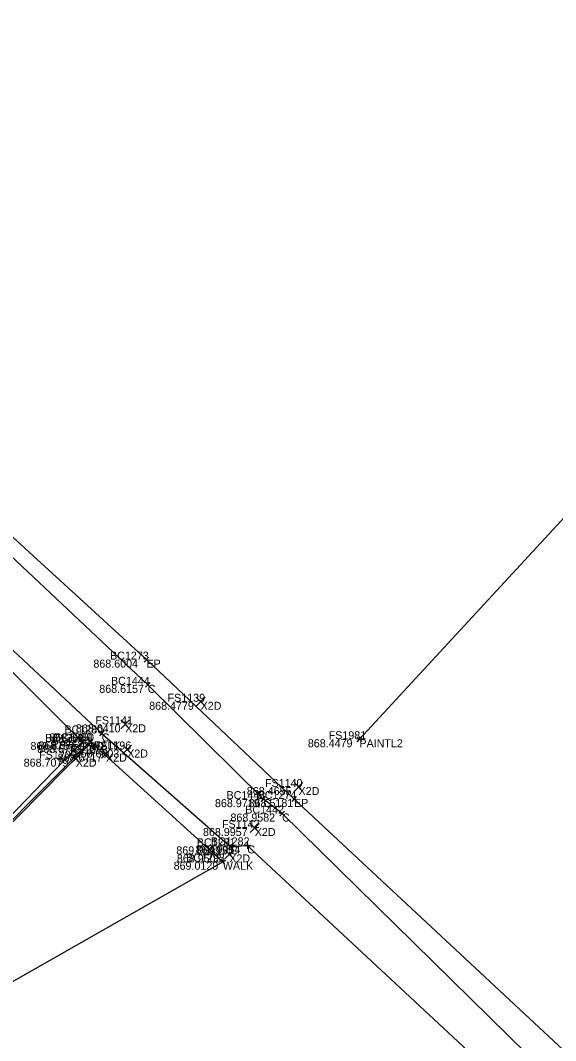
# Model space of a CAD drawing. Extents: x 1479425 to 1480294, y 379351 to 380102.
# Drawn here: x 1479658.52 to 1479662.53, y 379862.2 to 379869.84 of the extents above; entities that cross this region are included whole.
import ezdxf

# ---------------------------------------------------------------- set-up
doc = ezdxf.new("R2010")
doc.units = 0
for name, color, linetype in [('PM_X_Crosswalk', 7, 'Continuous'), ('PV_X_Curb', 7, 'Continuous'), ('PV_X_Walk', 7, 'Continuous'), ('RD_X_Concrete_Pad', 7, 'Continuous'), ('SV_X_Break_Lines', 7, 'Continuous'), ('SV_X_Random_Point', 7, 'Continuous'), ('SV_X_Shot_Marker', 7, 'Continuous'), ('SV_X_Text_Comment', 7, 'Continuous'), ('SV_X_Text_Elevation', 7, 'Continuous'), ('SV_X_Text_Name', 7, 'Continuous')]:
    doc.layers.add(name, color=color, linetype=linetype)

msp = doc.modelspace()

# ---------------------------------------------------------------- linework, layer by layer
at = {"layer": 'PM_X_Crosswalk'}
msp.add_lwpolyline([(1479661.061, 379864.4537), (1479696.232, 379902.5543)], dxfattribs=at)
at = {"layer": 'PV_X_Curb'}
for points in [[(1479674.4002, 379850.8088), (1479663.165, 379861.2618), (1479660.4814, 379863.897), (1479660.3417, 379864.0048), (1479659.4756, 379864.8615), (1479657.9728, 379866.276), (1479656.299, 379867.8605), (1479655.4781, 379868.4849), (1479655.3936, 379868.553), (1479653.3405, 379870.3718), (1479649.8028, 379873.0366), (1479644.8359, 379875.8815), (1479640.9714, 379876.9839), (1479637.7316, 379877.6879), (1479634.8886, 379878.0569), (1479629.5507, 379877.9769), (1479626.9417, 379877.5496), (1479624.927, 379877.2311), (1479623.2196, 379876.8713), (1479619.5522, 379875.9957), (1479615.007, 379874.7968)], [(1479644.7184, 379876.0341), (1479650.0207, 379873.0081), (1479655.5289, 379868.7448), (1479656.4303, 379867.8292), (1479659.4657, 379865.0505), (1479660.571, 379864.0064), (1479667.529, 379857.5214), (1479674.5498, 379850.8162), (1479681.356, 379844.5574), (1479695.384, 379831.4158), (1479709.512, 379818.1305), (1479724.003, 379804.7278), (1479730.662, 379798.2721), (1479750.68, 379779.6901), (1479759.253, 379771.8932), (1479760.555, 379770.78), (1479775.03, 379758.526), (1479788.183, 379747.5851), (1479800.537, 379737.2509), (1479801.677, 379736.2915)], [(1479644.5411, 379875.6244), (1479649.735, 379872.6614), (1479655.1572, 379868.3304), (1479655.2406, 379868.2948), (1479655.9122, 379867.6044), (1479656.2985, 379867.2898), (1479657.669, 379865.8645), (1479659.1303, 379864.4974), (1479660.094, 379863.6509), (1479660.2213, 379863.6582), (1479667.239, 379857.1215), (1479681.024, 379844.2076), (1479695.135, 379830.9784), (1479709.331, 379817.7082), (1479723.729, 379804.1927), (1479729.719, 379798.6), (1479748.963, 379780.548), (1479759.065, 379771.4845), (1479760.185, 379770.4729), (1479774.837, 379758.1297), (1479787.835, 379747.1604), (1479799.962, 379737.1088), (1479801.3, 379736.0452)]]:
    msp.add_lwpolyline(points, dxfattribs=at)
at = {"layer": 'PV_X_Walk'}
msp.add_lwpolyline([(1479656.4412, 379861.3061), (1479658.1736, 379862.4244), (1479658.2208, 379862.5019), (1479660.0376, 379863.5356), (1479659.0442, 379864.4378), (1479657.6587, 379863.0418), (1479657.5845, 379862.997), (1479656.1611, 379864.3595), (1479654.7505, 379865.7665), (1479654.8005, 379865.8361), (1479656.1025, 379867.2161), (1479655.8364, 379867.4576), (1479655.1823, 379868.1665), (1479654.209, 379866.3257), (1479654.1723, 379866.2342), (1479653.1639, 379864.2126), (1479653.1023, 379864.143), (1479653.0159, 379864.2566), (1479651.5463, 379865.5811), (1479650.1586, 379866.8771), (1479650.1004, 379866.9858), (1479648.689, 379868.2743), (1479647.1434, 379869.696)], dxfattribs=at)
at = {"layer": 'RD_X_Concrete_Pad'}
msp.add_lwpolyline([(1479656.1774, 379867.1692), (1479654.8041, 379865.7236), (1479656.2454, 379864.3988), (1479657.6462, 379863.0515), (1479658.9828, 379864.4335), (1479657.5266, 379865.8891)], close=True, dxfattribs=at)
at = {"layer": 'SV_X_Break_Lines'}
msp.add_lwpolyline([(1479659.0338, 379864.4109), (1479657.6127, 379862.9726), (1479656.567, 379861.8603)], dxfattribs=at)
at = {"layer": 'SV_X_Random_Point'}
for p, q in [((1479659.8377, 379864.7011), (1479659.9043, 379864.7679)), ((1479659.8377, 379864.7679), (1479659.9043, 379864.7011)), ((1479659.2727, 379864.5321), (1479659.3393, 379864.5989)), ((1479659.2727, 379864.5989), (1479659.3393, 379864.5321)), ((1479659.2877, 379864.3435), (1479659.3543, 379864.4103)), ((1479659.2877, 379864.4103), (1479659.3543, 379864.3435)), ((1479658.9027, 379864.2748), (1479658.9693, 379864.3416)), ((1479658.9027, 379864.3416), (1479658.9693, 379864.2748)), ((1479659.1297, 379864.3126), (1479659.1963, 379864.3794)), ((1479659.1297, 379864.3794), (1479659.1963, 379864.3126)), ((1479660.5717, 379864.0624), (1479660.6383, 379864.1292)), ((1479660.5717, 379864.1292), (1479660.6383, 379864.0624)), ((1479660.2437, 379863.755), (1479660.3103, 379863.8218)), ((1479660.2437, 379863.8218), (1479660.3103, 379863.755)), ((1479660.0527, 379863.5572), (1479660.1193, 379863.624)), ((1479660.0527, 379863.624), (1479660.1193, 379863.5572))]:
    msp.add_line(p, q, dxfattribs=at)
at = {"layer": 'SV_X_Shot_Marker'}
for p, q in [((1479659.4473, 379865.0674), (1479659.4841, 379865.0336)), ((1479659.4826, 379865.069), (1479659.4488, 379865.0321)), ((1479659.4657, 379865.0505), (1479659.4657, 379865.0505)), ((1479659.4934, 379864.8439), (1479659.4578, 379864.8791)), ((1479659.458, 379864.8437), (1479659.4932, 379864.8793)), ((1479659.4756, 379864.8615), (1479659.4756, 379864.8615)), ((1479659.112, 379864.5145), (1479659.1486, 379864.4803)), ((1479659.1474, 379864.5157), (1479659.1132, 379864.4792)), ((1479659.1303, 379864.4974), (1479659.1303, 379864.4974)), ((1479661.0426, 379864.4707), (1479661.0794, 379864.4368)), ((1479661.044, 379864.4353), (1479661.078, 379864.4721)), ((1479658.9648, 379864.4509), (1479659.0008, 379864.4161)), ((1479658.9654, 379864.4155), (1479659.0002, 379864.4515)), ((1479658.9828, 379864.4335), (1479658.9828, 379864.4335)), ((1479659.0516, 379864.3933), (1479659.016, 379864.4285)), ((1479659.0514, 379864.4287), (1479659.0162, 379864.3931)), ((1479659.0627, 379864.421), (1479659.0257, 379864.4546)), ((1479659.0274, 379864.4193), (1479659.061, 379864.4563)), ((1479659.0338, 379864.4109), (1479659.0338, 379864.4109)), ((1479659.0442, 379864.4378), (1479659.0442, 379864.4378)), ((1479661.061, 379864.4537), (1479661.061, 379864.4537)), ((1479660.3615, 379863.9895), (1479660.3219, 379864.0201)), ((1479660.3264, 379863.985), (1479660.357, 379864.0246)), ((1479660.5528, 379864.0236), (1479660.5892, 379863.9893)), ((1479660.5882, 379864.0246), (1479660.5538, 379863.9882)), ((1479660.3417, 379864.0048), (1479660.3417, 379864.0048)), ((1479660.571, 379864.0064), (1479660.571, 379864.0064)), ((1479660.4992, 379863.8795), (1479660.4636, 379863.9145)), ((1479660.4639, 379863.8792), (1479660.4989, 379863.9149)), ((1479660.4814, 379863.897), (1479660.4814, 379863.897)), ((1479660.0752, 379863.6674), (1479660.1128, 379863.6344)), ((1479660.1105, 379863.6697), (1479660.0775, 379863.6321)), ((1479660.094, 379863.6509), (1479660.094, 379863.6509)), ((1479660.1963, 379863.6568), (1479660.2463, 379863.6597)), ((1479660.2199, 379863.6832), (1479660.2227, 379863.6333)), ((1479660.2213, 379863.6582), (1479660.2213, 379863.6582)), ((1479660.0252, 379863.5573), (1479660.05, 379863.5139)), ((1479660.0159, 379863.5233), (1479660.0593, 379863.548)), ((1479660.0376, 379863.5356), (1479660.0376, 379863.5356))]:
    msp.add_line(p, q, dxfattribs=at)

# ---------------------------------------------------------------- texts
at = {"layer": 'SV_X_Text_Comment'}
for s, p in [('EP', (1479659.4657, 379864.9905)), ('C', (1479659.4756, 379864.8015)), ('X2D', (1479659.871, 379864.6745)), ('X2D', (1479659.306, 379864.5055)), ('C', (1479659.1303, 379864.4374)), ('PAD', (1479658.9828, 379864.3735)), ('B', (1479659.0338, 379864.3509)), ('WALK', (1479659.0442, 379864.3778)), ('PAINTL2', (1479661.061, 379864.3937)), ('X2D', (1479659.163, 379864.286)), ('X2D', (1479659.321, 379864.3169)), ('X2D', (1479658.936, 379864.2482)), ('X2D', (1479660.605, 379864.0358)), ('C', (1479660.3417, 379863.9448)), ('EP', (1479660.571, 379863.9464)), ('C', (1479660.4814, 379863.837)), ('X2D', (1479660.277, 379863.7284)), ('C', (1479660.094, 379863.5909)), ('C', (1479660.2213, 379863.5982)), ('X2D', (1479660.086, 379863.5306)), ('WALK', (1479660.0376, 379863.4756))]:
    msp.add_text(s, height=0.06, dxfattribs=at).set_placement(p)
at = {"layer": 'SV_X_Text_Elevation'}
for s, p in [('868.6004', (1479659.0679, 379864.9905)), ('868.6157', (1479659.1123, 379864.8015)), ('868.4779', (1479659.486, 379864.6745)), ('868.6410', (1479658.9371, 379864.5055)), ('868.6450', (1479658.7377, 379864.4374)), ('868.6757', (1479658.5968, 379864.3735)), ('868.6743', (1479658.6474, 379864.3509)), ('868.6662', (1479658.6559, 379864.3778)), ('868.4479', (1479660.6746, 379864.3937)), ('868.6717', (1479658.8007, 379864.286)), ('868.6603', (1479658.9275, 379864.3169)), ('868.7079', (1479658.5458, 379864.2482)), ('868.4655', (1479660.2176, 379864.0358)), ('868.9719', (1479659.9789, 379863.9448)), ('868.5181', (1479660.2312, 379863.9464)), ('868.9582', (1479660.095, 379863.837)), ('868.9957', (1479659.8891, 379863.7284)), ('869.0009', (1479659.6896, 379863.5909)), ('868.9954', (1479659.8339, 379863.5982)), ('868.9503', (1479659.6934, 379863.5306)), ('869.0129', (1479659.6691, 379863.4756))]:
    msp.add_text(s, height=0.06, dxfattribs=at).set_placement(p)
at = {"layer": 'SV_X_Text_Name'}
for s, p in [('BC1273', (1479659.1927, 379865.0505)), ('BC1444', (1479659.2002, 379864.8615)), ('FS1139', (1479659.624, 379864.7345)), ('FS1141', (1479659.0825, 379864.5655)), ('BC1280', (1479658.8511, 379864.4974)), ('BC1269', (1479658.7074, 379864.4335)), ('BC1290', (1479658.7537, 379864.4109)), ('BC1289', (1479658.7698, 379864.4378)), ('FS1981', (1479660.8308, 379864.4537)), ('FS1243', (1479658.8942, 379864.346)), ('FS1196', (1479659.0707, 379864.3769)), ('FS1209', (1479658.6616, 379864.3082)), ('FS1140', (1479660.3537, 379864.0958)), ('BC1443', (1479660.0659, 379864.0048)), ('BC1274', (1479660.2984, 379864.0064)), ('BC1442', (1479660.206, 379863.897)), ('FS1142', (1479660.0314, 379863.7884)), ('BC1281', (1479659.8426, 379863.6509)), ('BC1282', (1479659.9478, 379863.6582)), ('FS1195', (1479659.8395, 379863.5906)), ('BC1293', (1479659.7627, 379863.5356))]:
    msp.add_text(s, height=0.06, dxfattribs=at).set_placement(p)

doc.saveas('drawing.dxf')
